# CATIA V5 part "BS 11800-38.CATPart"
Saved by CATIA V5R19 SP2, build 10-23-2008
Part number: BS 11800-38
Bounding box of the stored display mesh (mm): x -74.81 to 74.81, y -74.81 to 74.81, z 0 to 154
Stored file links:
  C:\Users\Bora\Desktop\3D Katı model\BS serisi\BS 11800\BS 11800-38.CATPart
  C:\Program Files\Dassault Systemes\B19\intel_a\reffiles\standard\MetricThickPitch.txt
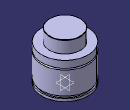
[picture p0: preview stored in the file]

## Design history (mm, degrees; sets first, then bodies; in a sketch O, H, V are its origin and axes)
Body1 (main body)
  Sketch1 on yz-plane, origin (0, 0, 0), H (0, 1, 0), V (0, 0, 1)
    point P1 (75, 93)
    point P2 (75, 88)
    point P5 (50, 153)
    point P7 (50, 153)
    point P12 (75, 88)
    point P13 (75, 93)
    arc A1 centre (75, 90.5) radius 2.5 from (75, 93) to (75, 88) ccw
    line L1 (75, 0) -> (75, 8)
    line L2 (50, 153) -> (50, 115)
    arc A2 centre (49, 153) radius 1 from (50, 153) to (49, 154) ccw
    line L3 (71, 15) -> (71, 8)
    line L4 (75, 15) -> (75, 88)
    line L5 (75, 93) -> (75, 115)
    line L6 (49, 154) -> (0, 154)
    point P15 (0, 154)
    line L7 (50, 115) -> (75, 115)
    line L8 (0, 0) -> (75, 0)
    line L9 (71, 15) -> (75, 15)
    line L10 (71, 8) -> (75, 8)
    coincidence: P15 V, P1 P13, P2 P12, P5 P7
    tangency: L6 A2
    horizontal: L7 H, L8 H, L9 H, L10 H
  Shaft1: profile Sketch1, axis Sketch1.V, angle 360
  Sketch2 on face of Shaft1 from Sketch1.L8, origin (0, 0, 0), H (1, 0, 0), V (0, -1, 0)
    point P1 (50, 0)
    distance P1 V = 50
  Hole1: placed by Sketch2, at (50, 0, 0) direction (0, 0, 1), diameter 8.376, depth 12, threaded "M10", thread diameter 10, thread depth 12, pitch 1.5
  CircPattern1: of Hole1, instances 4, angular step 90, axis from xy-plane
